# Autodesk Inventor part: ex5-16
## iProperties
Shininess: 64.0
Length Units: 11272
Angle Units: 11279
Time Units: 11290
Mass Units: 11286
Length Display Precision: 3
Angle Display Precision: 2
Compacted: True
Part Number: ex5-16
Document SubType Name: Modeling
Created: 2003-11
Designer: Elise Moss
Cost Center: 0.1 lbmass
Authority: 1.91 in^3
Manufacturer: Standard
Standards Organization: Custom
Density: 0.0
Volumn: 0.0
Area: 0.0
PropertySet Name: Model Information
Control State: 0
Master: False
Checked Out: False
SaveDate: 2003-11-15
SaveTime: 20:23
TotalMass: 0.1 lbmass
TotalVolume: 1.91 in^3
Author: Elise Moss
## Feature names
1. Loft1
2. Shell1
3. Extrusion1
4. Sweep1
5. Extrusion2
6. Coil1
7. Fillet1
8. Fillet2
9. FaceDraft1
